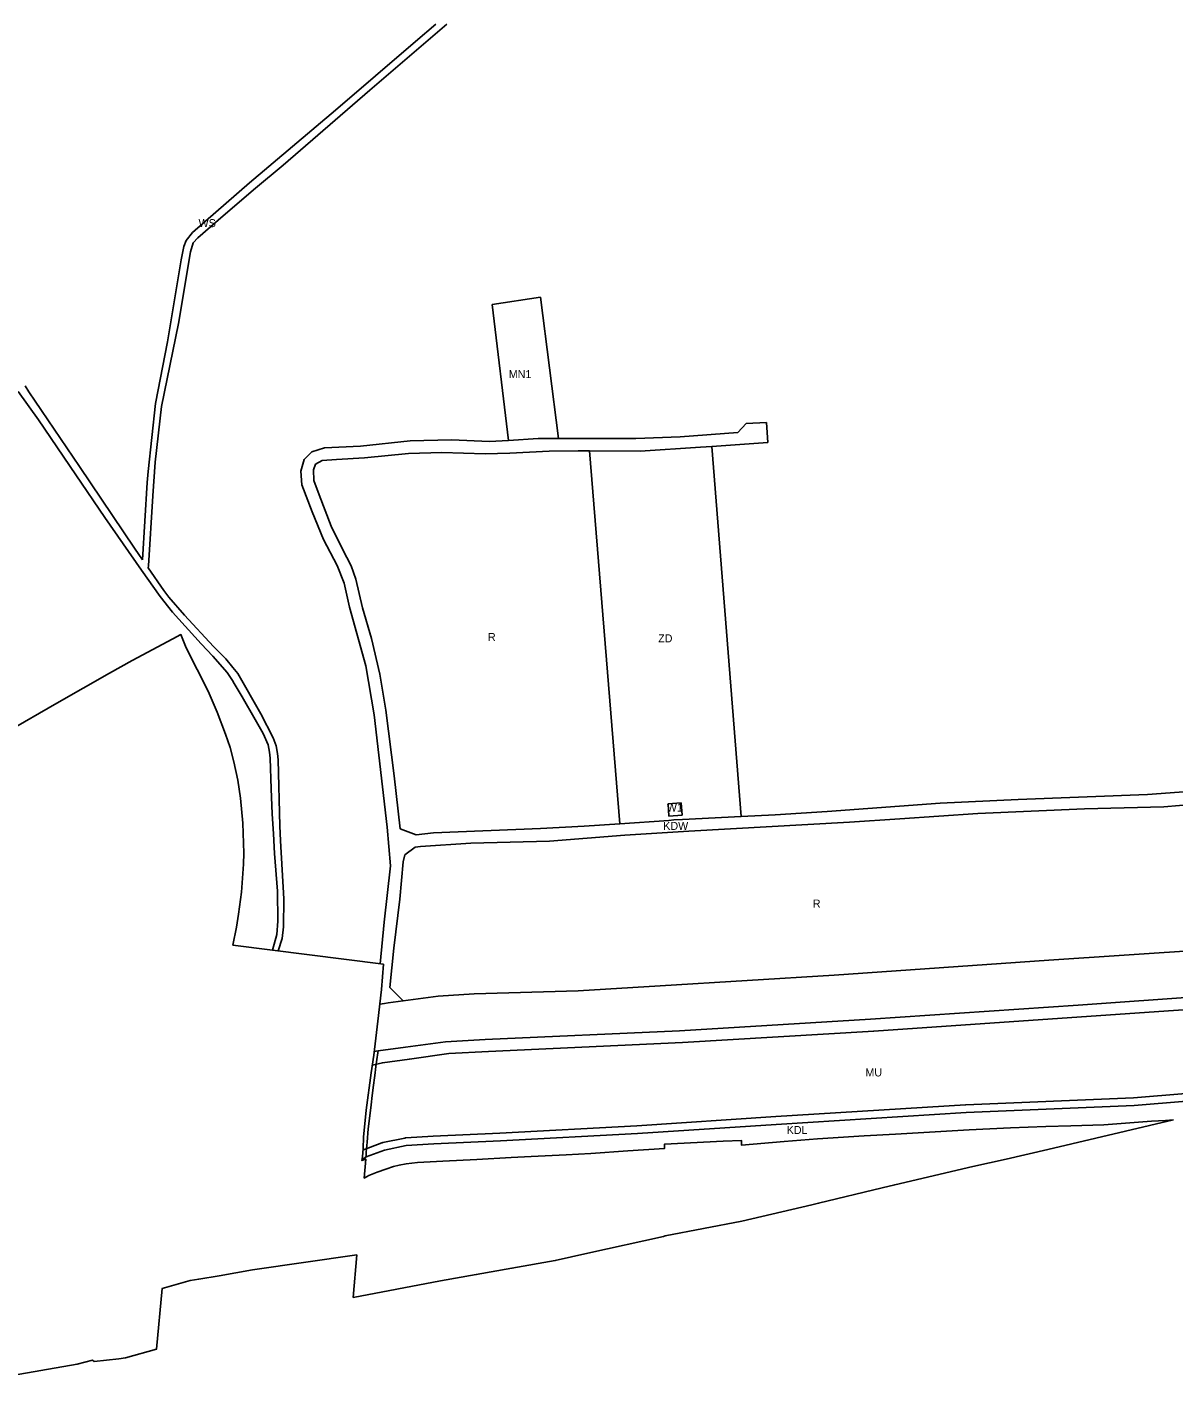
# Model space of a CAD drawing. Extents: x 7435758 to 7439981, y 5550649 to 5554049.
# Drawn here: x 7438071 to 7438816, y 5550930 to 5551818 of the extents above; entities that cross this region are included whole.
import ezdxf

# ---------------------------------------------------------------- set-up
doc = ezdxf.new("R2010")
doc.units = 0
for name, color, linetype in [('#Ruszcza', 7, 'Continuous'), ('linie_rozgraniczające', 7, 'Continuous'), ('linie_zabudowy_nieprzekraczalne', 7, 'Continuous'), ('oznaczenia_przeznaczen', 7, 'Continuous')]:
    doc.layers.add(name, color=color, linetype=linetype)

msp = doc.modelspace()

# ---------------------------------------------------------------- linework, layer by layer
at = {"layer": '#Ruszcza'}
for points in [[(7438816.43, 5551108.51), (7438811.14, 5551108.09), (7438801.98, 5551107.61), (7438771.08, 5551105.27), (7438749.54, 5551104.49), (7438733.29, 5551104.16), (7438710.5, 5551103.15), (7438683.51, 5551101.89), (7438635.63, 5551099.14), (7438615.39, 5551098.08), (7438584.96, 5551096.11), (7438563.41, 5551094.25), (7438535.66, 5551091.94), (7438535.57, 5551095.09), (7438523.58, 5551094.48), (7438485.51, 5551092.52), (7438485.51, 5551089.8), (7438461.74, 5551088.26), (7438437.58, 5551086.65), (7438421.71, 5551085.66), (7438398.88, 5551084.58), (7438385.82, 5551083.9), (7438363.66, 5551082.7), (7438341.51, 5551081.51), (7438325.07, 5551080.68), (7438317.74, 5551079.77), (7438313.07, 5551078.91), (7438309.44, 5551078.02), (7438304.53, 5551076.41), (7438298.86, 5551074.52), (7438293.51, 5551072.27), (7438290.42, 5551070.61), (7438291.41, 5551082.98), (7438288.87, 5551081.92), (7438289.26, 5551084.44), (7438289.7, 5551089.86), (7438289.94, 5551097.18), (7438291.59, 5551114.82), (7438295, 5551139.06), (7438296.6, 5551150.34), (7438299.22, 5551172.57), (7438301.64, 5551193.22), (7438302.89, 5551209.55), (7438205.05, 5551221.95), (7438207.32, 5551233.65), (7438208.61, 5551241.97), (7438210.65, 5551256.43), (7438211.97, 5551274.63), (7438212.19, 5551281.64), (7438211.48, 5551301.13), (7438209.91, 5551317.4), (7438208.33, 5551329.06), (7438205.64, 5551341.08), (7438203.26, 5551350.36), (7438200.24, 5551359), (7438194.79, 5551373.29), (7438188.91, 5551386.92), (7438174.61, 5551415.22), (7438171.24, 5551423.67), (7438166.05, 5551420.9), (7438139.63, 5551406.87), (7438124.88, 5551398.71), (7438090.73, 5551379.13), (7438058.41, 5551360.45)], [(7437990.62, 5550929.87), (7438103.91, 5550949.67), (7438113.81, 5550952.18), (7438114.95, 5550951.32), (7438131.01, 5550953.22), (7438135.18, 5550953.79), (7438155.5, 5550959.44), (7438159.01, 5550998.82), (7438177.28, 5551003.94), (7438182.92, 5551004.92), (7438196.16, 5551007.16), (7438217.88, 5551011.01), (7438285.51, 5551020.71), (7438283.23, 5550993.06), (7438340.08, 5551003.84), (7438363.24, 5551007.9), (7438386.39, 5551011.97), (7438414.57, 5551016.97), (7438435.63, 5551021.78), (7438484.93, 5551032.72), (7438485.91, 5551033.02), (7438535.86, 5551042.59), (7438581.26, 5551053.17), (7438585.63, 5551054.18), (7438627.04, 5551064.27), (7438635.17, 5551066.25), (7438685.83, 5551078.06), (7438707.57, 5551082.84), (7438734.59, 5551089.21), (7438816.43, 5551108.51)]]:
    msp.add_lwpolyline(points, dxfattribs=at)
at = {"layer": 'linie_rozgraniczające'}
for p, q in [((7438294.16, 5551777.35), (7438344.01, 5551820.38)), ((7438337.02, 5551820.28), (7438323.65, 5551809.14)), ((7438323.65, 5551809.14), (7438271.71, 5551764.41)), ((7438237.71, 5551728.66), (7438294.16, 5551777.35)), ((7438271.71, 5551764.41), (7438215.92, 5551717.18)), ((7438219.83, 5551713.75), (7438237.71, 5551728.66)), ((7438215.92, 5551717.18), (7438178.9, 5551685.08)), ((7438198.66, 5551695.84), (7438219.83, 5551713.75)), ((7438182.37, 5551681.54), (7438198.66, 5551695.84)), ((7438174.63, 5551679.7), (7438173.17, 5551675.87)), ((7438178.9, 5551685.08), (7438174.63, 5551679.7)), ((7438177.44, 5551672.46), (7438179.26, 5551678.36)), ((7438179.26, 5551678.36), (7438182.37, 5551681.54)), ((7438169.73, 5551625.93), (7438177.44, 5551672.46)), ((7438173.17, 5551675.87), (7438171.55, 5551667.19)), ((7438171.55, 5551667.19), (7438162.49, 5551613.97)), ((7438404.98, 5551642.99), (7438373.55, 5551638.09)), ((7438416.69, 5551551.17), (7438404.98, 5551642.99)), ((7438373.55, 5551638.09), (7438384.24, 5551549.91)), ((7438158.73, 5551571.9), (7438169.73, 5551625.93)), ((7438162.49, 5551613.97), (7438154.7, 5551573.89)), ((7438065.48, 5551581.68), (7438078.66, 5551563.27)), ((7438072.4, 5551581.37), (7438070.07, 5551585.42)), ((7438105.45, 5551532.88), (7438072.4, 5551581.37)), ((7438154.7, 5551573.89), (7438150.06, 5551529.61)), ((7438154.62, 5551535.84), (7438158.73, 5551571.9)), ((7438078.66, 5551563.27), (7438103.1, 5551527.46)), ((7438551.9, 5551561.56), (7438538.69, 5551560.87)), ((7438552.77, 5551548.57), (7438551.9, 5551561.56)), ((7438533.17, 5551555.11), (7438495.74, 5551552.2)), ((7438538.69, 5551560.87), (7438533.17, 5551555.11)), ((7438264.56, 5551545.13), (7438256.46, 5551542.56)), ((7438288.03, 5551546.08), (7438264.56, 5551545.13)), ((7438320.35, 5551549.63), (7438288.03, 5551546.08)), ((7438347.18, 5551550.35), (7438320.35, 5551549.63)), ((7438371.85, 5551549.11), (7438347.18, 5551550.35)), ((7438384.24, 5551549.91), (7438371.85, 5551549.11)), ((7438403.56, 5551551.14), (7438384.24, 5551549.91)), ((7438416.69, 5551551.17), (7438403.56, 5551551.14)), ((7438434.3, 5551551.2), (7438416.69, 5551551.17)), ((7438466.84, 5551551.03), (7438434.3, 5551551.2)), ((7438495.74, 5551552.2), (7438466.84, 5551551.03)), ((7438469.7, 5551542.93), (7438509, 5551545.42)), ((7438509, 5551545.42), (7438516.39, 5551545.95)), ((7438516.39, 5551545.95), (7438552.77, 5551548.57)), ((7438535.38, 5551305.53), (7438516.39, 5551545.95)), ((7438153.03, 5551513.93), (7438154.62, 5551535.84)), ((7438251.44, 5551537.51), (7438249.14, 5551529.96)), ((7438256.46, 5551542.56), (7438251.44, 5551537.51)), ((7438258.73, 5551534.37), (7438263.11, 5551536.94)), ((7438263.11, 5551536.94), (7438272.49, 5551537.47)), ((7438272.49, 5551537.47), (7438290.65, 5551538.5)), ((7438290.65, 5551538.5), (7438319.18, 5551541.45)), ((7438319.18, 5551541.45), (7438340.95, 5551542.04)), ((7438340.95, 5551542.04), (7438369.04, 5551541.09)), ((7438369.04, 5551541.09), (7438384.99, 5551541.59)), ((7438384.99, 5551541.59), (7438410.61, 5551542.92)), ((7438410.61, 5551542.92), (7438429.4, 5551543.09)), ((7438429.4, 5551543.09), (7438436.88, 5551543.06)), ((7438436.88, 5551543.06), (7438456.5, 5551300.82)), ((7438436.88, 5551543.06), (7438469.7, 5551542.93)), ((7438103.1, 5551527.46), (7438121.79, 5551499.8)), ((7438141.05, 5551479.77), (7438105.45, 5551532.88)), ((7438150.06, 5551529.61), (7438149.33, 5551522.61)), ((7438249.14, 5551529.96), (7438249.87, 5551521.03)), ((7438257.39, 5551530.74), (7438258.73, 5551534.37)), ((7438257.67, 5551523.88), (7438257.39, 5551530.74)), ((7438149.33, 5551522.61), (7438146.29, 5551472.31)), ((7438249.87, 5551521.03), (7438256.56, 5551503.39)), ((7438261.03, 5551514.47), (7438257.67, 5551523.88)), ((7438150.13, 5551468.46), (7438153.03, 5551513.93)), ((7438269.02, 5551494.2), (7438261.03, 5551514.47)), ((7438121.79, 5551499.8), (7438145.57, 5551465.54)), ((7438256.56, 5551503.39), (7438264, 5551485.41)), ((7438276.19, 5551479.27), (7438269.02, 5551494.2)), ((7438264, 5551485.41), (7438272.89, 5551468.61)), ((7438146.29, 5551472.31), (7438141.05, 5551479.77)), ((7438282, 5551468.46), (7438276.19, 5551479.27)), ((7438145.57, 5551465.54), (7438157.91, 5551448.48)), ((7438150.02, 5551467.01), (7438150.13, 5551468.46)), ((7438160.25, 5551452.47), (7438150.02, 5551467.01)), ((7438272.89, 5551468.61), (7438277.46, 5551457.23)), ((7438285.05, 5551459.63), (7438282, 5551468.46)), ((7438277.46, 5551457.23), (7438280.89, 5551441.52)), ((7438289.23, 5551441.15), (7438285.05, 5551459.63)), ((7438157.91, 5551448.48), (7438165.74, 5551438.23)), ((7438163.46, 5551447.98), (7438160.25, 5551452.47)), ((7438173.68, 5551436.25), (7438163.46, 5551447.98)), ((7438165.74, 5551438.23), (7438184.49, 5551417.75)), ((7438280.89, 5551441.52), (7438291.39, 5551403.51)), ((7438295.12, 5551421.09), (7438289.23, 5551441.15)), ((7438192.38, 5551415.96), (7438173.68, 5551436.25)), ((7438300.53, 5551398.03), (7438295.12, 5551421.09)), ((7438184.49, 5551417.75), (7438191.97, 5551409.72)), ((7438200.38, 5551407.94), (7438192.38, 5551415.96)), ((7438191.97, 5551409.72), (7438201.45, 5551399.06)), ((7438204.98, 5551402.3), (7438200.38, 5551407.94)), ((7438208.18, 5551398.33), (7438204.98, 5551402.3)), ((7438291.39, 5551403.51), (7438296.79, 5551371.65)), ((7438201.45, 5551399.06), (7438204.91, 5551393.83)), ((7438204.91, 5551393.83), (7438205.82, 5551391.94)), ((7438223.14, 5551372.26), (7438208.18, 5551398.33)), ((7438304.46, 5551374.61), (7438300.53, 5551398.03)), ((7438205.82, 5551391.94), (7438211.18, 5551383.22)), ((7438211.18, 5551383.22), (7438219.45, 5551368.6)), ((7438219.45, 5551368.6), (7438224.85, 5551359.55)), ((7438231.33, 5551356.57), (7438223.14, 5551372.26)), ((7438296.79, 5551371.65), (7438305.35, 5551298.5)), ((7438309.92, 5551332), (7438304.46, 5551374.61)), ((7438224.85, 5551359.55), (7438227.94, 5551352)), ((7438227.94, 5551352), (7438228.92, 5551347.4)), ((7438233.13, 5551351.35), (7438231.33, 5551356.57)), ((7438234.12, 5551346.36), (7438233.13, 5551351.35)), ((7438228.92, 5551347.4), (7438229.34, 5551343.38)), ((7438229.34, 5551343.38), (7438230.01, 5551323.5)), ((7438234.42, 5551342.4), (7438234.12, 5551346.36)), ((7438235.52, 5551299.41), (7438234.42, 5551342.4)), ((7438313.71, 5551297.53), (7438309.92, 5551332)), ((7438230.01, 5551323.5), (7438230.54, 5551307.29)), ((7438825.8, 5551321.67), (7438799.39, 5551319.85)), ((7438487.94, 5551313.78), (7438496.46, 5551314.51)), ((7438488.26, 5551305.79), (7438487.94, 5551313.78)), ((7438496.46, 5551314.51), (7438497.06, 5551306.38)), ((7438664.74, 5551314.2), (7438591.28, 5551308.79)), ((7438715.39, 5551316.63), (7438664.74, 5551314.2)), ((7438799.39, 5551319.85), (7438715.39, 5551316.63)), ((7438809.97, 5551311.88), (7438830.43, 5551313.46)), ((7438230.54, 5551307.29), (7438231.39, 5551294.31)), ((7438497.06, 5551306.38), (7438488.26, 5551305.79)), ((7438535.38, 5551305.53), (7438497.27, 5551303.55)), ((7438557.41, 5551306.67), (7438535.38, 5551305.53)), ((7438591.28, 5551308.79), (7438557.41, 5551306.67)), ((7438605.74, 5551301.92), (7438638.48, 5551303.99)), ((7438638.48, 5551303.99), (7438689.08, 5551307.54)), ((7438689.08, 5551307.54), (7438758.54, 5551310.54)), ((7438758.54, 5551310.54), (7438809.97, 5551311.88)), ((7438235.91, 5551289.65), (7438235.52, 5551299.41)), ((7438305.35, 5551298.5), (7438307.46, 5551273.52)), ((7438313.72, 5551297.45), (7438313.71, 5551297.53)), ((7438324.1, 5551293.67), (7438313.72, 5551297.45)), ((7438335.35, 5551294.86), (7438324.1, 5551293.67)), ((7438405, 5551297.69), (7438335.35, 5551294.86)), ((7438433.29, 5551299.21), (7438405, 5551297.69)), ((7438456.5, 5551300.82), (7438433.29, 5551299.21)), ((7438488.37, 5551303.03), (7438456.5, 5551300.82)), ((7438459.83, 5551293.39), (7438501.32, 5551296)), ((7438491.52, 5551303.25), (7438488.37, 5551303.03)), ((7438497.27, 5551303.55), (7438491.52, 5551303.25)), ((7438501.32, 5551296), (7438605.74, 5551301.92)), ((7438231.39, 5551294.31), (7438232.2, 5551281.4)), ((7438238.22, 5551252.07), (7438235.91, 5551289.65)), ((7438323.52, 5551285.53), (7438326.93, 5551286.13)), ((7438326.93, 5551286.13), (7438359.68, 5551288.2)), ((7438359.68, 5551288.2), (7438410.74, 5551289.53)), ((7438410.74, 5551289.53), (7438459.83, 5551293.39)), ((7438232.2, 5551281.4), (7438234.12, 5551256.95)), ((7438315.78, 5551275.97), (7438316.9, 5551280.59)), ((7438316.9, 5551280.59), (7438323.52, 5551285.53)), ((7438307.46, 5551273.52), (7438303.38, 5551236.86)), ((7438313.59, 5551251.82), (7438315.78, 5551275.97)), ((7438234.12, 5551256.95), (7438234.19, 5551237.61)), ((7438237.85, 5551233.84), (7438238.22, 5551252.07)), ((7438309.66, 5551219.95), (7438313.59, 5551251.82)), ((7438234.19, 5551237.61), (7438233.69, 5551228.91)), ((7438237.04, 5551226.25), (7438237.85, 5551233.84)), ((7438303.38, 5551236.86), (7438300.69, 5551209.83)), ((7438233.69, 5551228.91), (7438230.82, 5551218.68)), ((7438234.59, 5551218.26), (7438237.04, 5551226.25)), ((7438234.57, 5551218.21), (7438234.59, 5551218.26)), ((7438307.04, 5551194.5), (7438309.66, 5551219.95)), ((7438850.71, 5551219.79), (7438735.34, 5551212.15)), ((7438735.34, 5551212.15), (7438595.91, 5551202.43)), ((7438595.91, 5551202.43), (7438482.67, 5551195.4)), ((7438315.64, 5551185.67), (7438307.04, 5551194.5)), ((7438338.56, 5551188.74), (7438315.64, 5551185.67)), ((7438361.88, 5551190.33), (7438338.56, 5551188.74)), ((7438429.53, 5551192.27), (7438361.88, 5551190.33)), ((7438482.67, 5551195.4), (7438429.53, 5551192.27)), ((7438754.39, 5551183.04), (7438850.43, 5551189.67)), ((7438303.67, 5551184.07), (7438300.5, 5551183.52)), ((7438306, 5551184.38), (7438303.67, 5551184.07)), ((7438315.64, 5551185.67), (7438306, 5551184.38)), ((7438619.48, 5551173.83), (7438754.39, 5551183.04)), ((7438495.22, 5551166.35), (7438619.48, 5551173.83)), ((7438369.1, 5551160.58), (7438495.22, 5551166.35)), ((7438296.9, 5551152.92), (7438299.39, 5551153.17)), ((7438299.39, 5551153.17), (7438299.23, 5551151.96)), ((7438299.39, 5551153.17), (7438299.56, 5551153.21)), ((7438299.56, 5551153.21), (7438317.33, 5551155.56)), ((7438317.33, 5551155.56), (7438343.17, 5551159.2)), ((7438343.17, 5551159.2), (7438369.1, 5551160.58)), ((7438298.67, 5551147.65), (7438298.06, 5551143)), ((7438299.23, 5551151.96), (7438298.67, 5551147.65)), ((7438297.05, 5551135.62), (7438296.4, 5551130.95)), ((7438297.54, 5551139.03), (7438297.05, 5551135.62)), ((7438297.81, 5551141.07), (7438297.54, 5551139.03)), ((7438298.06, 5551143), (7438297.81, 5551141.07)), ((7438296.4, 5551130.95), (7438295.57, 5551124.22)), ((7438294.84, 5551118.2), (7438293.97, 5551111.11)), ((7438295.57, 5551124.22), (7438294.84, 5551118.2)), ((7438790.72, 5551117.67), (7438681.49, 5551113.24)), ((7438824.79, 5551120.59), (7438790.72, 5551117.67)), ((7438293.97, 5551111.11), (7438293.05, 5551102.61)), ((7438681.49, 5551113.24), (7438558.17, 5551105.5)), ((7438293.05, 5551102.61), (7438292.33, 5551093.97)), ((7438467.96, 5551099.54), (7438378.87, 5551094.87)), ((7438558.17, 5551105.5), (7438467.96, 5551099.54)), ((7438811.8, 5551107.42), (7438811.82, 5551107.42)), ((7438292.33, 5551093.97), (7438291.77, 5551087.32)), ((7438317.73, 5551091.69), (7438303.64, 5551088.74)), ((7438335.55, 5551092.77), (7438317.73, 5551091.69)), ((7438378.87, 5551094.87), (7438335.55, 5551092.77)), ((7438289.63, 5551083.15), (7438289.01, 5551082.81)), ((7438291.51, 5551084.19), (7438289.63, 5551083.15)), ((7438291.6, 5551085.29), (7438291.51, 5551084.19)), ((7438291.77, 5551084.34), (7438291.51, 5551084.19)), ((7438291.77, 5551087.32), (7438291.6, 5551085.29)), ((7438303.64, 5551088.74), (7438291.77, 5551084.34))]:
    msp.add_line(p, q, dxfattribs=at)
msp.add_lwpolyline([(7438816.43, 5551108.51), (7438811.14, 5551108.09), (7438801.98, 5551107.61), (7438771.08, 5551105.27), (7438749.54, 5551104.49), (7438733.29, 5551104.16), (7438710.5, 5551103.15), (7438683.51, 5551101.89), (7438635.63, 5551099.14), (7438615.39, 5551098.08), (7438584.96, 5551096.11), (7438563.41, 5551094.25), (7438535.66, 5551091.94), (7438535.57, 5551095.09), (7438523.58, 5551094.48), (7438485.51, 5551092.52), (7438485.51, 5551089.8), (7438461.74, 5551088.26), (7438437.58, 5551086.65), (7438421.71, 5551085.66), (7438398.88, 5551084.58), (7438385.82, 5551083.9), (7438363.66, 5551082.7), (7438341.51, 5551081.51), (7438325.07, 5551080.68), (7438317.74, 5551079.77), (7438313.07, 5551078.91), (7438309.44, 5551078.02), (7438304.53, 5551076.41), (7438298.86, 5551074.52), (7438293.51, 5551072.27), (7438290.42, 5551070.61), (7438291.41, 5551082.98), (7438288.87, 5551081.92), (7438289.26, 5551084.44), (7438289.7, 5551089.86), (7438289.94, 5551097.18), (7438291.59, 5551114.82), (7438295, 5551139.06), (7438296.6, 5551150.34), (7438299.22, 5551172.57), (7438301.64, 5551193.22), (7438302.89, 5551209.55), (7438205.05, 5551221.95), (7438207.32, 5551233.65), (7438208.61, 5551241.97), (7438210.65, 5551256.43), (7438211.97, 5551274.63), (7438212.19, 5551281.64), (7438211.48, 5551301.13), (7438209.91, 5551317.4), (7438208.33, 5551329.06), (7438205.64, 5551341.08), (7438203.26, 5551350.36), (7438200.24, 5551359), (7438194.79, 5551373.29), (7438188.91, 5551386.92), (7438174.61, 5551415.22), (7438171.24, 5551423.67), (7438166.05, 5551420.9), (7438139.63, 5551406.87), (7438124.88, 5551398.71), (7438090.73, 5551379.13), (7438058.41, 5551360.45)], dxfattribs=at)
at = {"layer": 'linie_zabudowy_nieprzekraczalne'}
for points in [[(7438876.16, 5551183.58), (7438756.48, 5551175.32), (7438756.48, 5551175.32), (7438621.57, 5551166.11), (7438621.53, 5551166.1), (7438497.27, 5551158.63), (7438497.19, 5551158.62), (7438371.1, 5551152.86), (7438345.4, 5551151.49), (7438319.78, 5551147.88), (7438319.74, 5551147.87), (7438302.24, 5551145.56), (7438295.69, 5551143.96)], [(7438289.81, 5551088.93), (7438289.98, 5551089), (7438290.04, 5551089.03), (7438301.9, 5551093.43), (7438302.15, 5551093.51), (7438302.47, 5551093.6), (7438302.61, 5551093.63), (7438316.71, 5551096.59), (7438316.88, 5551096.62), (7438317.21, 5551096.67), (7438317.43, 5551096.68), (7438335.24, 5551097.76), (7438335.3, 5551097.76), (7438378.62, 5551099.87), (7438467.67, 5551104.53), (7438557.84, 5551110.49), (7438557.86, 5551110.49), (7438681.18, 5551118.23), (7438681.29, 5551118.23), (7438790.4, 5551122.66), (7438824.25, 5551125.56)]]:
    msp.add_lwpolyline(points, dxfattribs=at)

# ---------------------------------------------------------------- texts
at = {"layer": 'oznaczenia_przeznaczen'}
for s, p in [('WS', (7438182.76, 5551688.45)), ('MN1', (7438384.36, 5551590.36)), ('R', (7438370.81, 5551419.57)), ('ZD', (7438481.45, 5551418.67)), ('W1', (7438487.05, 5551308.74)), ('KDW', (7438484.75, 5551296.82)), ('R', (7438581.92, 5551246.36)), ('MU', (7438616.12, 5551136.62)), ('KDL', (7438564.95, 5551099.24))]:
    msp.add_text(s, height=5.2, dxfattribs=at).set_placement(p)

doc.saveas('drawing.dxf')
